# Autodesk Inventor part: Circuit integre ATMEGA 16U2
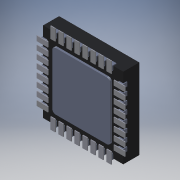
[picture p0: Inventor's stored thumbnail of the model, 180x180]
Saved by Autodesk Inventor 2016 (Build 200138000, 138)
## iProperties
Created: 2018-03
Part Number: Circuit integre ATMEGA 16U2
Material: Générique
Document SubType Name: Modeling
Designer: Bruno
Density: 1 g/cm^3
Appearance: Par défaut
Author: Bruno
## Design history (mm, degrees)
feature "Composite1"
body "Srf1"
